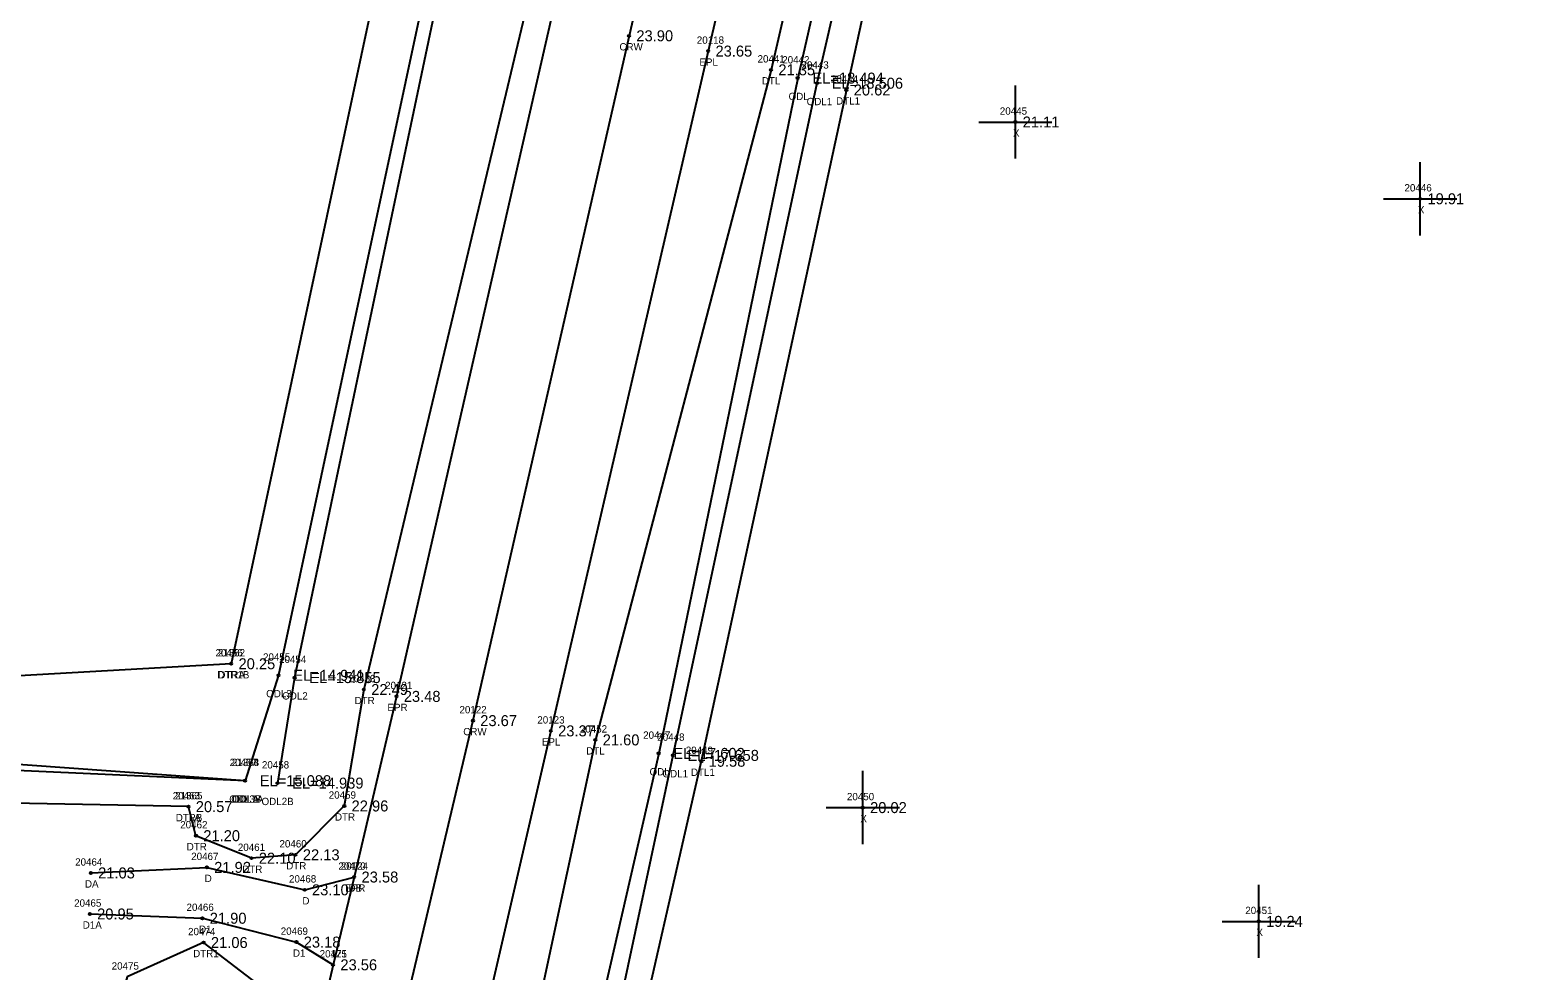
# Model space of a CAD drawing. Extents: x 2655177 to 2656219, y 761780 to 764748.
# Drawn here: x 2655730 to 2655936, y 763539 to 763667.6 of the extents above; entities that cross this region are included whole.
import ezdxf

# ---------------------------------------------------------------- set-up
doc = ezdxf.new("R2010")
doc.units = 0
for name, color, linetype in [('RD_DTM_BkLn1', 7, 'Continuous'), ('RD_EX_Driveway', 7, 'Continuous'), ('RD_EX_Driveway_txCode', 7, 'Continuous'), ('RD_EX_H2O', 7, 'Continuous'), ('RD_EX_H2O_txCode', 7, 'Continuous'), ('RD_EX_Misc', 7, 'Continuous'), ('RD_EX_Misc_txCode', 7, 'Continuous'), ('RD_EX_Road', 7, 'Continuous'), ('RD_EX_Road_txCode', 7, 'Continuous'), ('RD_EX_TX_Driveway_ELEV', 7, 'Continuous'), ('RD_EX_TX_H2O_ELEV', 7, 'Continuous'), ('RD_EX_TX_Misc_ELEV', 7, 'Continuous'), ('RD_EX_TX_Road_ELEV', 7, 'Continuous'), ('RD_HC_Survey_ELEV', 7, 'Continuous'), ('RD_HC_Survey_txCode', 7, 'Continuous'), ('RD_SMD_Locator', 7, 'Continuous')]:
    doc.layers.add(name, color=color, linetype=linetype)

msp = doc.modelspace()

# ---------------------------------------------------------------- linework, layer by layer
at = {"layer": 'RD_DTM_BkLn1'}
msp.add_lwpolyline([(2656052.36, 764720.46), (2656029.22, 764619.66), (2656007.41, 764523.97), (2655985.61, 764427.64), (2655963.53, 764330.64), (2655941.2, 764233.56), (2655920.06, 764141.06), (2655898.52, 764047.86), (2655877.71, 763954.88), (2655855.89, 763859.81), (2655834.07, 763763.97), (2655811.81, 763666.79), (2655790.48, 763573.22), (2655769.27, 763483.63), (2655747.64, 763389.32), (2655725.4, 763293.96), (2655721.51, 763275.9)], dxfattribs=at)
at = {"layer": 'RD_EX_Driveway'}
for points in [[(2655738.27, 763552.41), (2655754.13, 763553.17), (2655767.49, 763550.1), (2655774.26, 763551.85)], [(2655738.13, 763546.8), (2655753.52, 763546.22), (2655766.36, 763542.96), (2655771.37, 763539.86)]]:
    msp.add_lwpolyline(points, dxfattribs=at)
at = {"layer": 'RD_EX_H2O'}
for points in [[(2655815.89, 763850.53), (2655830, 763850.66), (2655835.07, 763845.39), (2655815.37, 763767.48), (2655802.69, 763714.59), (2655797.51, 763669.56), (2655775.58, 763577.47), (2655772.9, 763561.56), (2655766.24, 763554.89), (2655760.22, 763554.42), (2655752.64, 763557.5), (2655751.61, 763561.47)], [(2655815.89, 763850.53), (2655812.51, 763836.78), (2655816.76, 763833.86), (2655801.46, 763772.79), (2655777.62, 763675.45), (2655757.45, 763580.99)], [(2655820.56, 763845.54), (2655824.97, 763844.01), (2655808.26, 763770.16), (2655784.18, 763674.18), (2655763.92, 763579.41), (2655759.35, 763565.01)], [(2655827.33, 763843.31), (2655809.9, 763769.59), (2655786.05, 763673.96), (2655766.11, 763579.1), (2655763.77, 763564.68)], [(2655866.2, 763781.92), (2655858.43, 763782.12), (2655853.29, 763757.63), (2655831.21, 763662.14), (2655807.21, 763570.59), (2655787.76, 763479.91), (2655766.41, 763384.86), (2655751.38, 763287.62), (2655745.55, 763261.6)], [(2655866.2, 763781.92), (2655866.81, 763773.88), (2655862.68, 763756.12), (2655841.51, 763659.39), (2655821.68, 763567.67), (2655800.98, 763476.96), (2655780.09, 763381.34), (2655766.41, 763289.68), (2655763.83, 763255.61)], [(2655859.17, 763772.66), (2655856.61, 763756.77), (2655834.86, 763661.01), (2655815.86, 763568.74), (2655795.14, 763478.35), (2655775.69, 763381.88), (2655758.88, 763290.93), (2655758.58, 763269.84), (2655756.39, 763249.8)], [(2655862.03, 763772.5), (2655859.51, 763756.17), (2655837.49, 763660.31), (2655817.79, 763568.47), (2655798.48, 763478.03), (2655777.42, 763381.75), (2655761.98, 763290.17), (2655758.58, 763269.84)], [(2655757.45, 763580.99), (2655680.96, 763576.66), (2655578.06, 763571.44), (2655470.41, 763559.47), (2655370.94, 763554.75), (2655276.75, 763546.33)], [(2655759.35, 763565.01), (2655680.83, 763570.66), (2655578.54, 763563.45), (2655471.45, 763555.87), (2655371.16, 763549.76), (2655277.06, 763543.35)], [(2655759.35, 763565.01), (2655680.78, 763568.55), (2655578.67, 763561.21), (2655471.72, 763553.89), (2655371.24, 763547.95), (2655277.37, 763540.37)], [(2655751.61, 763561.47), (2655681.52, 763562.81), (2655578.85, 763554.88), (2655473.08, 763549.56), (2655371.46, 763543.69), (2655277.89, 763535.39)], [(2655761.66, 763536.79), (2655753.68, 763542.9), (2655743.24, 763538.2), (2655729.93, 763492.02), (2655706.75, 763396.29), (2655684.97, 763303.64), (2655679.52, 763275.1)]]:
    msp.add_lwpolyline(points, dxfattribs=at)
at = {"layer": 'RD_EX_Misc'}
for p, q in [((2655864.59, 763650.01), (2655864.59, 763660.01)), ((2655859.59, 763655.01), (2655869.59, 763655.01)), ((2655919.9, 763639.52), (2655919.9, 763649.52)), ((2655914.9, 763644.52), (2655924.9, 763644.52)), ((2655843.74, 763556.34), (2655843.74, 763566.34)), ((2655838.74, 763561.34), (2655848.74, 763561.34)), ((2655897.85, 763540.79), (2655897.85, 763550.79)), ((2655892.85, 763545.79), (2655902.85, 763545.79))]:
    msp.add_line(p, q, dxfattribs=at)
at = {"layer": 'RD_EX_Road'}
for points in [[(2656041.72, 764723.31), (2656018.5, 764622.03), (2656002.75, 764552.49), (2655997.43, 764530.02), (2655974.74, 764429.64), (2655952.97, 764333.57), (2655930.52, 764235.7), (2655909.18, 764142.93), (2655887.93, 764050.57), (2655866.91, 763957.26), (2655846.82, 763869.53), (2655845.21, 763862.22), (2655839.99, 763839.71), (2655823.38, 763766.66), (2655801.33, 763669.93), (2655780.03, 763576.53), (2655774.26, 763551.85), (2655771.37, 763539.86), (2655759.09, 763486.9), (2655736.94, 763391.72), (2655715.19, 763296.77), (2655711.35, 763278.45)], [(2655930.84, 764138.62), (2655926.81, 764121.01), (2655909.26, 764045.26), (2655908.15, 764039.87), (2655902.08, 764013.51), (2655888.19, 763952.26), (2655880.73, 763919.6), (2655875, 763893.73), (2655866.73, 763857), (2655852.89, 763796.34), (2655850.73, 763786.52), (2655844.88, 763760.97), (2655822.62, 763664.7), (2655801.12, 763571.82), (2655780.32, 763481.64), (2655758.16, 763386.38), (2655736.73, 763291.27), (2655733.33, 763273.46)]]:
    msp.add_lwpolyline(points, dxfattribs=at)
at = {"layer": 'RD_SMD_Locator'}
for centre in [(2655811.81, 763666.79), (2655822.62, 763664.7), (2655831.21, 763662.14), (2655834.86, 763661.01), (2655837.49, 763660.31), (2655841.51, 763659.39), (2655864.59, 763655.01), (2655919.9, 763644.52), (2655757.45, 763580.99), (2655757.45, 763580.99), (2655763.92, 763579.41), (2655766.11, 763579.1), (2655775.58, 763577.47), (2655780.03, 763576.53), (2655790.48, 763573.22), (2655801.12, 763571.82), (2655807.21, 763570.59), (2655815.86, 763568.74), (2655817.79, 763568.47), (2655821.68, 763567.67), (2655759.35, 763565.01), (2655759.35, 763565.01), (2655759.35, 763565.01), (2655763.77, 763564.68), (2655751.61, 763561.47), (2655751.61, 763561.47), (2655772.9, 763561.56), (2655843.74, 763561.34), (2655752.64, 763557.5), (2655760.22, 763554.42), (2655766.24, 763554.89), (2655738.27, 763552.41), (2655754.13, 763553.17), (2655774.26, 763551.85), (2655774.26, 763551.85), (2655767.49, 763550.1), (2655738.13, 763546.8), (2655753.52, 763546.22), (2655897.85, 763545.79), (2655753.68, 763542.9), (2655766.36, 763542.96), (2655771.37, 763539.86), (2655771.37, 763539.86)]:
    msp.add_circle(centre, 0.15, dxfattribs=at)

# ---------------------------------------------------------------- texts
at = {"layer": 'RD_EX_Driveway_txCode'}
for s, p in [('20464', (2655736.13, 763553.41)), ('20467', (2655751.99, 763554.17)), ('20470', (2655772.1, 763552.85)), ('DA', (2655737.47, 763550.41)), ('D', (2655753.83, 763551.17)), ('20468', (2655765.35, 763551.1)), ('DB', (2655773.48, 763549.85)), ('20465', (2655735.99, 763547.8)), ('20466', (2655751.35, 763547.22)), ('D', (2655767.18, 763548.1)), ('D1A', (2655737.17, 763544.8)), ('D1', (2655753.05, 763544.22)), ('20469', (2655764.22, 763543.96)), ('D1', (2655765.89, 763540.96)), ('20471', (2655769.54, 763540.86))]:
    msp.add_text(s, height=1, dxfattribs=at).set_placement(p)
at = {"layer": 'RD_EX_H2O_txCode'}
for s, p in [('20441', (2655829.37, 763663.14)), ('20442', (2655832.74, 763663.01)), ('20443', (2655835.37, 763662.31)), ('DTL', (2655829.96, 763660.14)), ('20444', (2655839.39, 763660.39)), ('ODL', (2655833.61, 763658.01)), ('ODL1', (2655836.08, 763657.31)), ('DTL1', (2655840.1, 763657.39)), ('20456', (2655755.31, 763581.99)), ('21362', (2655755.63, 763581.99)), ('20455', (2655761.8, 763581.41)), ('20454', (2655763.99, 763581.1)), ('DTR1B', (2655755.55, 763578.99)), ('DTRA', (2655755.7, 763578.99)), ('20453', (2655773.46, 763578.47)), ('ODL3', (2655762.23, 763576.41)), ('ODL2', (2655764.42, 763576.1)), ('DTR', (2655774.31, 763575.47)), ('20452', (2655805.09, 763571.59)), ('20447', (2655813.74, 763570.74)), ('20448', (2655815.67, 763570.47)), ('DTL', (2655805.96, 763568.59)), ('20449', (2655819.56, 763568.67)), ('20457', (2655757.24, 763567.01)), ('21363', (2655757.54, 763567.01)), ('21364', (2655757.54, 763567.01)), ('20458', (2655761.65, 763566.68)), ('ODL', (2655814.61, 763565.74)), ('ODL1', (2655816.38, 763565.47)), ('DTL1', (2655820.27, 763565.67)), ('20463', (2655749.47, 763562.47)), ('21365', (2655749.8, 763562.47)), ('ODL3B', (2655757.19, 763562.01)), ('ODL1A', (2655757.46, 763562.01)), ('ODLA', (2655757.62, 763562.01)), ('ODL2B', (2655761.6, 763561.68)), ('20459', (2655770.78, 763562.56)), ('DTRB', (2655749.87, 763559.47)), ('DTLA', (2655749.88, 763559.47)), ('20462', (2655750.49, 763558.5)), ('DTR', (2655771.63, 763559.56)), ('DTR', (2655751.37, 763555.5)), ('20460', (2655764.05, 763555.89)), ('20461', (2655758.36, 763555.42)), ('DTR', (2655758.96, 763552.42)), ('DTR', (2655764.97, 763552.89)), ('20474', (2655751.56, 763543.9)), ('20475', (2655741.12, 763539.2)), ('DTR1', (2655752.25, 763540.9))]:
    msp.add_text(s, height=1, dxfattribs=at).set_placement(p)
at = {"layer": 'RD_EX_Misc_txCode'}
for s, p in [('20445', (2655862.47, 763656.01)), ('X', (2655864.27, 763653.01)), ('20446', (2655917.76, 763645.52)), ('X', (2655919.59, 763642.52)), ('20450', (2655841.58, 763562.34)), ('X', (2655843.42, 763559.34)), ('20451', (2655896.01, 763546.79)), ('X', (2655897.53, 763543.79))]:
    msp.add_text(s, height=1, dxfattribs=at).set_placement(p)
at = {"layer": 'RD_EX_Road_txCode'}
for s, p in [('20118', (2655821.07, 763665.7)), ('EPL', (2655821.42, 763662.7)), ('20121', (2655778.48, 763577.53)), ('EPR', (2655778.8, 763574.53)), ('20123', (2655799.28, 763572.82)), ('EPL', (2655799.91, 763569.82)), ('20124', (2655772.43, 763552.85)), ('EPR', (2655773.03, 763549.85)), ('20125', (2655769.54, 763540.86))]:
    msp.add_text(s, height=1, dxfattribs=at).set_placement(p)
at = {"layer": 'RD_EX_TX_Driveway_ELEV'}
for s, p in [('21.03', (2655739.27, 763551.66)), ('21.92', (2655755.13, 763552.42)), ('23.58', (2655775.26, 763551.1)), ('23.10', (2655768.49, 763549.35)), ('20.95', (2655739.13, 763546.05)), ('21.90', (2655754.52, 763545.47)), ('23.18', (2655767.36, 763542.21)), ('23.56', (2655772.37, 763539.11))]:
    msp.add_text(s, height=1.5, dxfattribs=at).set_placement(p)
at = {"layer": 'RD_EX_TX_H2O_ELEV'}
for s, p in [('21.35', (2655832.21, 763661.39)), ('EL=18.494', (2655836.86, 763660.26)), ('EL=18.506', (2655839.49, 763659.56)), ('20.62', (2655842.51, 763658.64)), ('20.25', (2655758.45, 763580.24)), ('20.25', (2655758.45, 763580.24)), ('EL=14.941', (2655765.92, 763578.66)), ('EL=15.855', (2655768.11, 763578.35)), ('22.49', (2655776.58, 763576.72)), ('21.60', (2655808.21, 763569.84)), ('EL=17.602', (2655817.86, 763567.99)), ('EL=17.658', (2655819.79, 763567.72)), ('19.58', (2655822.68, 763566.92)), ('EL=15.088', (2655761.35, 763564.26)), ('EL=15.088', (2655761.35, 763564.26)), ('EL=15.088', (2655761.35, 763564.26)), ('EL=14.939', (2655765.77, 763563.93)), ('20.57', (2655752.61, 763560.72)), ('20.57', (2655752.61, 763560.72)), ('22.96', (2655773.9, 763560.81)), ('21.20', (2655753.64, 763556.75)), ('22.10', (2655761.22, 763553.67)), ('22.13', (2655767.24, 763554.14)), ('21.06', (2655754.68, 763542.15))]:
    msp.add_text(s, height=1.5, dxfattribs=at).set_placement(p)
at = {"layer": 'RD_EX_TX_Misc_ELEV'}
for s, p in [('21.11', (2655865.59, 763654.26)), ('19.91', (2655920.9, 763643.77)), ('20.02', (2655844.74, 763560.59)), ('19.24', (2655898.85, 763545.04))]:
    msp.add_text(s, height=1.5, dxfattribs=at).set_placement(p)
at = {"layer": 'RD_EX_TX_Road_ELEV'}
for s, p in [('23.65', (2655823.62, 763663.95)), ('23.48', (2655781.03, 763575.78)), ('23.37', (2655802.12, 763571.07)), ('23.58', (2655775.26, 763551.1)), ('23.56', (2655772.37, 763539.11))]:
    msp.add_text(s, height=1.5, dxfattribs=at).set_placement(p)
at = {"layer": 'RD_HC_Survey_ELEV'}
for s, p in [('23.90', (2655812.81, 763666.04)), ('23.67', (2655791.48, 763572.47))]:
    msp.add_text(s, height=1.5, dxfattribs=at).set_placement(p)
at = {"layer": 'RD_HC_Survey_txCode'}
for s, p in [('CRW', (2655810.5, 763664.79)), ('20122', (2655788.64, 763574.22)), ('CRW', (2655789.16, 763571.22))]:
    msp.add_text(s, height=1, dxfattribs=at).set_placement(p)

doc.saveas('drawing.dxf')
